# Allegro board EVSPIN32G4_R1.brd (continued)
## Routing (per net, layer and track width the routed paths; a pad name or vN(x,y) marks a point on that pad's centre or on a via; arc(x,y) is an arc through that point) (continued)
USB_DM: length 14.8
  TOP w0.305: U4.6 12.42,40.8 12.83,40.39 12.83,34.87 15.6,32.1 U5.32
USB_DP: length 17.2
  TOP w0.305: U4.4 11.88,34.68 14.72,31.84 ; U5.33 15.1,31.46 14.72,31.84 ; 14.72,31.84 R104.1
USB_RENUM: length 5.8
  TOP w0.254: R102.2 11.4,28.42 13.17,26.64 13.17,26 13.01,25.84 U5.38
V: length 34.6
  TOP w0.508: R58.1 R20.2 75.28,34 79.47,38.19 v1(80.52,38.19)
  PWR w0.508: v1(80.52,38.19) 82.55,40.23 97.88,40.23 v1(98.77,39.34)
  vias: v1(96.87,24.35) v1(96.87,23.59) v1(97.76,24.73) v1(97.76,23.72) v1(97.76,22.7) v1(98.77,38.32) v1(99.19,38.83) v1(99.41,24.73) v1(99.41,23.72) v1(99.41,22.7) v1(99.66,39.34) v1(99.66,38.32) v1(100.08,38.83) v1(100.55,39.34) v1(100.55,38.32) v1(100.97,38.83) v1(101.06,24.73) v1(101.06,23.72) v1(101.06,22.7) v1(101.44,39.34) v1(101.44,38.32) v1(101.95,24.35) v1(101.95,23.59)
VHALL: length 17.6
  TOP w0.508: C37.2 55.72,61.22 J6.4
  BOTTOM w0.762: 50.26,62.71 50.26,61.05 ; 50.26,62.71 50.51,62.45 50.53,62.45 ; 50.26,62.71 50.26,64.36 ; R84.1 50.53,62.45 ; R84.1 R89.1 ; R84.1 R87.1 ; 50.53,62.45 54.2,62.45 J6.4
VM: length 180.3
  TOP w0.508: R76.1 128.25,59.67 ; R37.2 v2(36.8,31.02)
  TOP w0.835: 102.02,58.45 C32.1 ; C32.1 104.42,58.45 ; C32.1 102.02,56.04 ; C32.1 104.42,56.04 ; C33.1 118.01,56.04 ; C33.1 115.61,58.45 ; C33.1 118.01,58.45 ; C33.1 115.61,56.04 ; 132,45.4 CON2.2 ; CON2.2 134.94,45.4 ; CON2.2 134.94,48.34 ; CON2.2 132,48.34 ; 127,45.4 CON2.1 ; CON2.1 129.94,45.4 ; CON2.1 127,48.34 ; CON2.1 129.94,48.34 ; 88.43,58.45 C31.1 ; C31.1 90.83,58.45 ; C31.1 88.43,56.04 ; C31.1 90.83,56.04
  PWR w0.381: v2(36.8,31.02) 37.62,30.19 43.53,30.19 45.18,31.84 48.05,31.84 52.58,36.37
  PWR w0.835: C33.1 118.01,58.45 ; C33.1 118.01,56.04 ; C33.1 115.61,58.45 ; C33.1 115.61,56.04 ; CON2.2 134.94,45.4 ; CON2.2 132,48.34 ; CON2.2 132,45.4 ; CON2.2 134.94,48.34 ; 102.02,58.45 C32.1 ; C32.1 102.02,56.04 ; C32.1 104.42,58.45 ; C32.1 104.42,56.04 ; CON2.1 129.94,48.34 ; CON2.1 129.94,45.4 ; CON2.1 127,45.4 ; CON2.1 127,48.34 ; C31.1 90.83,58.45 ; C31.1 88.43,58.45 ; C31.1 88.43,56.04 ; C31.1 90.83,56.04
  PWR w0.889: v2(84.42,46.96) 72.48,35.02 53.93,35.02 50.18,38.77 50.18,40.48 48.35,42.31 v2(48.35,43.53)
  BOTTOM w0.508: v2(48.35,43.53) 48.48,43.4 R1.1
  BOTTOM w0.835: C31.1 90.83,58.45 ; C31.1 90.83,56.04 ; C31.1 88.43,56.04 ; C31.1 88.43,58.45 ; CON2.2 134.94,45.4 ; CON2.2 132,45.4 ; CON2.2 134.94,48.34 ; CON2.2 132,48.34 ; 102.02,58.45 C32.1 ; C32.1 102.02,56.04 ; C32.1 104.42,56.04 ; C32.1 104.42,58.45 ; 115.61,58.45 C33.1 ; C33.1 118.01,58.45 ; C33.1 115.61,56.04 ; C33.1 118.01,56.04 ; 127,48.34 CON2.1 ; CON2.1 129.94,48.34 ; CON2.1 129.94,45.4 ; CON2.1 127,45.4
  vias: v2(82.77,59.15) v2(84.42,48.35) v2(84.84,44.42) v2(84.84,42.39) v2(85.06,47.59) v2(85.69,48.35) v2(85.69,46.96) v2(86.33,50.39) v2(86.33,47.59) v2(86.33,43.4) v2(86.96,48.35) v2(86.96,46.96) v2(87.6,47.59) v2(87.88,44.42) v2(87.88,42.39) v2(88.23,48.35) v2(88.23,46.96) v2(97.5,48.35) v2(97.5,46.96) v2(97.92,44.42) v2(97.92,42.39) v2(98.14,47.59) v2(98.77,48.35) v2(98.77,46.96) v2(99.41,50.39) v2(99.41,47.59) v2(99.41,43.4) v2(100.04,48.35) v2(100.04,46.96) v2(100.68,47.59) v2(100.97,44.42) v2(100.97,42.39) v2(101.31,48.35) v2(101.31,46.96) v2(110.58,48.35) v2(110.58,46.96) v2(111,44.42) v2(111,42.39) v2(111.22,47.59) v2(111.85,48.35) v2(111.85,46.96) v2(112.49,50.39) v2(112.49,47.59) v2(112.49,43.4) v2(113.12,48.35) v2(113.12,46.96) v2(113.76,47.59) v2(114.05,44.42) v2(114.05,42.39) v2(114.39,48.35) v2(114.39,46.96) v2(137.63,59.15)
VREF+: length 175
  TOP w0.279: 53.42,28.17 U1.26
  TOP w0.305: 53.46,28.14 53.42,28.17
  TOP w0.381: 53.46,28.14 53.46,26.56 v2(53.31,26.41)
  TOP w0.508: R43.2 v2(50.26,19.65) ; v2(53.31,26.41) 53.81,25.9 53.81,25.51 C10.2 54.23,25.46 54.83,24.86 54.83,23.17 C11.1 ; R42.2 v2(44.42,19.65) ; R41.2 v2(35.27,28.03) ; TR1.1 19.02,58.9 24.99,58.9 CN5.8
  TOP w0.762: CN5.8 27.69,56.2 C30.1 27.69,29.01 31.34,25.37 v2(34.13,25.37)
  PWR w0.305: v2(93.31,11.78) 93.18,11.91 92.17,11.91 90.52,10.25 83.41,10.25 76.29,17.37 74.39,17.37 v2(74.13,17.62)
  PWR w0.762: v2(34.13,25.37) 34.13,26.89 v2(35.27,28.03) 36.54,28.03 39.08,25.49 52.52,25.49 53.43,26.41 ; J5.6 48.48,4.54 49.62,4.54 52.16,7.08 52.16,19.4 51.91,19.65 ; 53.43,26.41 v2(53.31,26.41) ; 53.43,26.41 53.43,26.89 54.32,27.78 55.47,27.78 56.23,27.02 56.23,24.99 55.72,24.48 55.72,22.83 52.54,19.65 51.91,19.65 ; 51.91,19.65 v2(50.26,19.65) 49.12,20.8 45.56,20.8 v2(44.42,19.65)
  BOTTOM w0.305: v2(74.13,17.62) 66.64,17.62 63.21,21.05 58.41,21.05 53.31,26.16 v2(53.31,26.41) ; NTC1.1 94.14,11.78 v2(93.31,11.78)
  BOTTOM w0.508: R9.1 52.91,26.8 v2(53.31,26.41)
VREGIN: length 83.1
  TOP w0.762: 36.16,2.63 38.69,5.16 v1(47.58,5.16)
  TOP w1.016: J5.2 36.16,2.89 33.88,5.17 31.21,5.17 28.74,7.64 v1(28.74,8.63) v1(28.18,9.19)
  PWR w0.889: v1(48.4,39.97) 47.91,39.97 v1(47.72,40.16)
  PWR w1.016: v1(47.72,40.16) 47.53,40.35 42.64,40.35 41.75,39.46 41.75,37.94 41.03,37.22 39.67,37.22 37.94,38.96 30.57,38.96 26.51,34.89 26.51,20.67 24.48,18.64 24.48,12.89 v1(28.18,9.19) v1(28.74,8.63)
  BOTTOM w0.508: R66.1 v1(47.58,5.16)
  BOTTOM w0.762: v1(48.4,39.97) 48.1,39.97 46.96,41.12 R6.1
VSHUNT1N: length 92.8
  TOP w0.305: R50.1 31.84,26.38 v1(31.65,26.57) ; v1(44.92,13.97) 45.44,13.97 49.29,10.13 77.82,10.13 79.22,8.73 105.25,8.73 108.55,12.03 112.63,12.03 v1(113,11.67)
  BOTTOM w0.305: v1(44.92,13.97) 44.33,14.57 43.02,14.57 32.21,25.39 32.21,26.02 v1(31.65,26.57) ; v1(113,11.67) NET1.1
VSHUNT1P: length 92.5
  TOP w0.305: v1(44.92,15.21) 49.5,10.64 78.02,10.64 79.42,9.24 105.04,9.24 108.34,12.54 112.63,12.54 v1(113,12.9) ; R44.1 32.48,28.03 32.47,28.02 31.87,28.02 v1(31.65,27.81)
  BOTTOM w0.305: v1(44.92,15.21) 43.1,15.21 32.71,25.6 32.71,26.75 v1(31.65,27.81)
  vias: v1(109.98,14.86) v1(110.36,15.49) v1(110.74,14.86) v1(111.12,15.49) v1(111.51,14.86) v1(111.85,19.65) v1(112.36,19.15) v1(112.74,19.65) v1(113.25,19.15) v1(113.63,19.65) v1(114.14,19.15) v1(114.43,14.86) v1(114.52,19.65) v1(114.81,15.49) v1(115.19,14.86) v1(115.57,15.49) v1(115.95,14.86)
VSHUNT2N: length 60.1
  TOP w0.305: R51.1 48.06,17.18 46.77,15.88 46.77,14.89 50.39,11.27 79.47,11.27 80.87,9.87 94.84,9.87 97,12.03 99.55,12.03 v1(99.92,11.67)
  BOTTOM w0.305: v1(99.92,11.67) NET2.1
VSHUNT2P: length 59.7
  TOP w0.305: v1(47.46,15.43) 47.46,14.91 50.6,11.78 79.68,11.78 81.08,10.38 94.63,10.38 96.79,12.54 99.55,12.54 v1(99.92,12.9) ; v1(46.32,16.67) 44.92,16.67 R45.1
  BOTTOM w0.305: v1(46.32,16.67) 47.46,15.53 v1(47.46,15.43)
  vias: v1(96.9,14.86) v1(97.28,15.49) v1(97.66,14.86) v1(98.04,15.49) v1(98.43,14.86) v1(98.77,19.65) v1(99.28,19.15) v1(99.66,19.65) v1(100.17,19.15) v1(100.55,19.65) v1(101.06,19.15) v1(101.35,14.86) v1(101.44,19.65) v1(101.73,15.49) v1(102.11,14.86) v1(102.49,15.49) v1(102.87,14.86)
VSHUNT3N: length 39.7
  TOP w0.305: R52.1 51.38,16.52 51.38,16.07 54.53,12.92 80.94,12.92 81.83,12.03 v1(86.58,12.03)
  BOTTOM w0.305: NET3.1 86.83,11.78 v1(86.58,12.03)
VSHUNT3P: length 41.3
  TOP w0.305: R46.1 50.26,16.48 54.32,12.42 80.74,12.42 81.62,11.53 85.34,11.53 v1(85.71,11.16)
  BOTTOM w0.305: v1(85.71,11.16) 85.71,12.45 R35.2
  vias: v1(83.82,14.86) v1(84.2,15.49) v1(84.58,14.86) v1(84.96,15.49) v1(85.34,14.86) v1(85.69,19.65) v1(86.2,19.15) v1(86.58,19.65) v1(87.09,19.15) v1(87.47,19.65) v1(87.98,19.15) v1(88.36,19.65) v1(88.39,14.86) v1(88.77,15.49) v1(89.15,14.86) v1(89.54,15.49) v1(89.92,14.86)
W: length 51
  TOP w0.508: R60.1 R21.2 72.64,27.65 81.66,36.67 81.66,38.32 82.68,39.34 v1(85.73,39.34)
  TOP w0.581: CON1.5 129.67,36.9 ; CON1.5 127.27,36.9 ; CON1.5 129.67,34.5 ; CON1.5 128.47,34.08 ; CON1.5 128.47,37.33 ; CON1.5 126.84,35.7 ; CON1.5 130.09,35.7 ; CON1.5 127.27,34.5 ; 132.27,34.5 CON1.6 ; CON1.6 134.67,34.5 ; CON1.6 134.67,36.9 ; CON1.6 135.09,35.7 ; CON1.6 133.47,34.08 ; CON1.6 131.84,35.7 ; CON1.6 132.27,36.9 ; CON1.6 133.47,37.33
  vias: v1(83.79,24.35) v1(83.79,23.59) v1(84.68,24.73) v1(84.68,23.72) v1(84.68,22.7) v1(85.06,34.77) v1(85.06,32.23) v1(85.06,29.69) v1(85.06,27.15) v1(85.73,38.32) v1(86.11,38.83) v1(86.33,34.77) v1(86.33,32.23) v1(86.33,29.69) v1(86.33,27.15) v1(86.33,24.73) v1(86.33,23.72) v1(86.33,22.7) v1(86.61,39.34) v1(86.61,38.32) v1(87,38.83) v1(87.5,39.34) v1(87.5,38.32) v1(87.6,34.77) v1(87.6,32.23) v1(87.6,29.69) v1(87.6,27.15) v1(87.88,38.83) v1(87.98,24.73) v1(87.98,23.72) v1(87.98,22.7) v1(88.39,39.34) v1(88.39,38.32) v1(88.87,24.35) v1(88.87,23.59)
N170257: length 1.3
  TOP w0.508: D5.2 69.09,17.81 R22.1
N170269: length 46.2
  TOP w0.508: R25.2 68.8,16.41 R22.2 70.77,16.41 73.25,18.89 v1(74.13,18.89)
  PWR w0.508: v1(74.13,18.89) 79.34,18.89 81.12,17.11 105,17.11 108.45,20.56 v1(109.82,20.56)
  BOTTOM w0.508: R28.2 109.02,20.56 v1(109.82,20.56) Q4.4
N170415: length 43.9
  TOP w0.508: v1(109.86,40.1) 109.86,40.22 109.08,40.99 79.41,40.99 78.33,42.07 R10.2 68.8,42.07 R13.2
  BOTTOM w0.508: R16.2 109,40.1 v1(109.86,40.1) 110.43,40.1 Q1.4
N170423: length 1.3
  TOP w0.508: R10.1 70.26,43.53 D2.2
N174120: length 31.8
  TOP w0.508: v1(71.47,19.72) R23.2 68.8,19.72 R26.2
  PWR w0.508: v1(71.47,19.72) 79.66,19.72 81.5,17.87 92.68,17.87 95.37,20.56 v1(96.74,20.56)
  BOTTOM w0.508: R29.2 95.94,20.56 v1(96.74,20.56) Q5.4
N174124: length 1.3
  TOP w0.508: R23.1 69.09,21.11 D6.2
N174270: length 31.7
  TOP w0.508: R14.2 68.8,35.72 R11.2 75.98,35.72 79.34,39.08 80.9,39.08 82.04,40.23 93.57,40.23 v1(94.45,39.34)
  BOTTOM w0.508: v1(94.45,39.34) 94.45,39.59 95.03,40.16 R17.2 95.94,40.25 Q2.4
N174282: length 1.3
  TOP w0.508: D3.2 69.09,37.12 R11.1
N174784: length 18.8
  TOP w0.508: v1(83.66,20.54) 76.67,20.54 74.2,23.02 R24.2 68.8,23.02 R27.2
  BOTTOM w0.508: v1(83.66,20.54) 83.6,20.48 R30.2 82.86,20.56 Q6.4
N174788: length 1.3
  TOP w0.508: D7.2 69.09,24.42 R24.1
N174934: length 21.7
  TOP w0.508: v1(80.52,37.18) 80.52,36.54 73.34,29.37 R12.2 68.8,29.37 R15.2
  BOTTOM w0.508: v1(80.52,37.18) 80.9,37.18 81.41,37.69 81.41,39.34 82.23,40.16 R18.2 82.86,40.25 Q3.4
N174946: length 1.3
  TOP w0.508: R12.1 69.09,30.77 D4.2
N180167: length 2.8
  TOP w0.254: U5.2 14.1,17.97 R116.1
N180187: length 4.7
  TOP w0.254: U5.3 14.6,16.7 R117.1
N180745: length 5.9
  TOP w0.279: R106.2 19.72,15.92 ; 19.72,15.92 R105.1 ; 19.72,15.92 19.78,15.99 19.78,17.24 18.64,18.38 18.25,18.38 18.1,18.54 U5.10
N180799: length 4.1
  TOP w0.279: R114.1 18.95,30.26 18.1,29.4 U5.27
N180929: length 3.9
  TOP w0.305: J8.3 7.21,39.46 7.77,38.9 U4.3
N180941: length 4
  TOP w0.305: J8.2 7.22,40.11 7.9,40.8 U4.1
N181071: length 2
  TOP w0.305: Q7.2 8.46,31.77 R104.2
N181167: length 5.6
  TOP w0.305: Q7.1 6.63,29.94 R103.2 R102.1 9.94,27.02 R101.1
N181233: length 3.7
  TOP w0.254: U5.39 9.96,25.34 R110.1 R107.2
N181269: length 2.6
  TOP w0.508: C47.2 21.39,38.7 U3.4
N181591: length 1.3
  TOP w0.305: 2,48.48 1.94,48.42 R121.2
N181595: length 1.3
  TOP w0.305: 6.32,48.48 6.38,48.42 R122.2
N181645: length 9.3
  TOP w0.254: U5.5 15.6,18.65 15.08,18.13 15.08,14.61 C48.1 14.03,11.04 X2.1
N181657: length 9
  TOP w0.254: X2.2 15.37,11.04 C49.1 15.59,13.77 15.59,18 16.1,18.51 U5.6
N181761: length 2.4
  TOP w0.279: R119.2 10.46,22.84 U5.44
N258505: length 15.6
  TOP w0.305: J6.1 63.34,63.59 57.75,58.01 57.75,55.28 58.42,54.61 58.42,52.48
  TOP w0.381: R78.2 R81.1
N258509: length 15.4
  TOP w0.305: J6.2 60.8,63.59 55.21,58.01 55.21,54.74 55.37,54.58 55.37,52.48
  TOP w0.381: R79.2 R82.1
N258513: length 16.4
  TOP w0.305: 52.29,52.48 52.29,54.2 52.67,54.58 52.67,58.13 53.94,59.4 55.47,59.4 58.26,62.2 J6.3
  TOP w0.381: R83.1 R80.2
N261648: length 31.1
  TOP w0.305: R92.1 33.02,38.48 C40.1 33.02,41.72 R90.1 30.86,43.94 30.86,57.66 28.07,60.45 SW3.1
  TOP w0.508: SW3.2 SW3.1
N262399: length 85.7
  TOP w0.305: SW2.1 48.24,60.61 R95.1 50.45,60.61 51.27,61.44 51.27,64.23 52.55,65.5 70.71,65.5 71.09,65.12 71.09,59.53 69.82,58.26 v1(69.82,52.42) ; 58.92,23.99 59.04,24.1 59.53,24.1 v1(60.16,24.73)
  TOP w0.381: 58.92,23.99 58.92,22.33 C39.1 58.93,20.7 R97.1 ; 58.92,23.99 58.92,24.13 R96.1 ; 58.92,23.99 58.91,23.97 58.89,23.98
  TOP w0.508: SW2.1 SW2.2
  BOTTOM w0.305: v1(69.82,52.42) 69.82,30.83 63.72,24.73 v1(60.16,24.73)
N265543: length 2.3
  TOP w0.508: R77.1 R76.2
N265547: length 1.7
  TOP w0.508: LED1.2 R77.2
N274832: length 3.2
  BOTTOM w0.381: R65.1 33.62,8.08 CN6.2
N274924: length 2.4
  BOTTOM w0.381: CN6.8 48.86,6.2 R66.2
N274964: length 4.6
  BOTTOM w0.305: CN8.4 61.56,8.85 61.05,9.35 R73.1 R70.1
N274968: length 4.5
  BOTTOM w0.305: 64.1,11.02 65.11,11.02 R74.1 ; 64.1,11.02 CN8.5 ; 64.1,11.02 63.1,11.02 R71.1
N274972: length 4.6
  BOTTOM w0.305: CN8.6 67.15,9.11 R72.1 R75.1
N520147: length 1.5
  TOP w0.305: R95.2 50,63.47
N538821: length 2.4
  BOTTOM w0.305: R67.1 CN8.1
N539050: length 55.4
  BOTTOM w0.305: R69.1 36.67,38.58 34.03,35.94 34.03,32.51 30.73,29.21 30.73,25.59 40.26,16.07 40.26,14.42 41.85,12.83 51.31,12.83 52.45,13.97 55.44,13.97 57.37,12.03 57.37,10.25 CN8.3 58.89,8.6
N539062: length 55.9
  BOTTOM w0.305: R68.1 37.81,40.48 33.49,36.16 33.49,32.73 30.19,29.43 30.19,25.37 39.72,15.84 39.72,14.19 41.62,12.29 51.53,12.29 52.67,13.43 55.21,13.43 56.48,12.16 CN8.2
N683197: length 26.3
  TOP w0.279: 33.05,44.9 C38.1
  TOP w0.305: 34.04,60.45 33.4,59.82 33.4,51.69 33.05,51.34 R93.1 R91.1
  TOP w0.381: SW1.1 39.05,60.45 R94.1
  TOP w0.508: SW1.1 SW1.2
N683205: length 1.5
  TOP w0.381: R94.2 39.21,63.47
N684002: length 17.2
  TOP w0.305: C21.2 13.94,55.3 v1(13.94,56.48) TR1.2 11.65,66.26 TP3.1
  BOTTOM w0.305: R38.2 13.92,56.47 v1(13.94,56.48)
N685395: length 26.3
  TOP w0.279: v1(63.02,53.05) 63.02,52.74
  TOP w0.305: U2.7 63.4,51.79 R98.2 63.02,52.74
  BOTTOM w0.305: J7.1 70.36,53.21 68.23,53.21 66.96,51.94 64.13,51.94 v1(63.02,53.05)
N685399: length 22.8
  TOP w0.305: U2.6 64.05,51.79 R98.1 v1(64.42,53.05)
  BOTTOM w0.305: v1(64.42,53.05) 64.9,52.58 66.71,52.58 67.85,53.72 69.98,53.72 78.58,62.32 J7.2
N685471: length 2.3
  BOTTOM w0.381: R100.2 73.5,62.57 J7.4
N728166: length 35.5
  TOP w0.305: v1(65.24,32.48) R58.2 ; R59.1 v1(35.4,34.38)
  BOTTOM w0.305: v1(35.4,34.38) 36.29,35.27 40.35,35.27 41.11,36.04 42.77,36.04 47.18,31.62 64.39,31.62 v1(65.24,32.48)
N728550: length 37.7
  TOP w0.305: R61.1 v1(35.4,32.61) ; v1(64.77,28.57) R60.2
  BOTTOM w0.305: v1(35.4,32.61) 36.29,33.5 39.46,33.5 41.5,35.53 42.51,35.53 46.96,31.08 62.26,31.08 v1(64.77,28.57)
N729020: length 38.3
  TOP w0.305: v1(65.12,36.42) 65.12,37.31 66.64,38.83 R56.2 ; R57.1 v1(35.4,36.16)
  BOTTOM w0.305: v1(65.12,36.42) 60.86,32.16 47.4,32.16 42.51,37.05 36.29,37.05 v1(35.4,36.16)
N741558: length 2.2
  TOP w0.508: R105.2 v1(21.94,16.73)
  BOTTOM w0.508: v1(21.94,16.73) R108.2
N741774: length 5.3
  TOP w0.279: U1.61 50.42,41.5 50.26,41.66
  TOP w0.635: C2.2 49.75,42.39 v1(50.26,41.88) 50.26,41.66
  BOTTOM w0.508: v1(50.26,41.88) 50.51,42.13 50.51,43.26 R1.2

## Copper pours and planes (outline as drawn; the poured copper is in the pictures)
3V3_STLINK on TOP (solid shape): 3.96,52.29 0.66,52.29 0.66,55.74 3.96,55.74
3V3_STLINK on PWR: 22.83,43.02 22.83,11.52 22.57,11.27 10.76,11.27 2.13,19.91 2.13,28.8 16.6,43.27 22.57,43.27
GND on TOP (solid shape): 7.66,52.29 4.36,52.29 4.36,55.74 7.66,55.74
GND on TOP: 45.05,39.59 45.05,40.61 44.67,40.99 44.04,40.99 43.65,41.37 43.65,42.77 43.27,42.77 41.5,44.54 41.11,44.54 40.86,44.29 40.86,42.77 44.04,39.59
GND on TOP: 20.41,44.16 20.41,36.8 18.25,36.8 18.25,40.23 17.62,40.23 17.62,40.73 18.25,40.73 18.25,44.16
GND on TOP: 0.35,44.93 8.48,44.93 8.6,44.8 8.6,34.13 8.48,34 0.35,34 0.22,34.13 0.22,44.8
GND on TOP: 43.78,45.81 43.91,45.94 43.91,47.72 44.8,48.61 44.8,50.64 40.1,50.64 39.84,50.39 39.84,45.94 39.97,45.81
GND on TOP: 82.52,8.22 82.64,8.35 117.19,8.35 117.31,8.22 117.31,1.11 117.19,0.98 82.64,0.98 82.52,1.11
GND on TOP, BOTTOM, PWR: 125.19,60.67 125.19,66.13 124.93,66.39 84.17,66.39 83.91,66.13 83.91,60.67 84.17,60.42 124.93,60.42
GND on BOTTOM: 104.74,41.75 104.74,43.53 104.87,43.66 106.65,43.66 107.03,43.27 107.03,42 106.65,41.62 104.87,41.62
GND on BOTTOM: 117.82,41.75 117.82,43.53 117.95,43.66 119.73,43.66 120.11,43.27 120.11,42 119.73,41.62 117.95,41.62
GND on BOTTOM: 91.66,41.75 91.66,43.53 91.79,43.66 93.57,43.66 93.95,43.27 93.95,42 93.57,41.62 91.79,41.62
GND on BOTTOM, PWR: 82.64,8.73 117.19,8.73 117.31,8.6 117.31,1.11 117.19,0.98 82.64,0.98 82.52,1.11 82.52,8.6
GND on GND: 0.86,1.11 0.86,66.13 1.11,66.39 82.39,66.39 82.64,66.13 82.64,61.94 70.74,50.04 70.74,48.62 60.9,38.83 60.67,38.83 57.5,35.65 56.74,35.65 56.74,30.96 56.48,30.7 54.58,30.7 54.58,28.03 55.97,26.64 60.04,26.64 65.24,21.43 65.24,16.99 70.83,11.4 70.83,1.11 70.58,0.98 70.61,1.02 0.95,1.02 ; 1 cut-out
GND on GND: 70.96,1.11 70.96,11.52 65.37,17.11 65.37,21.56 60.16,26.76 56.1,26.76 54.7,28.16 54.7,30.83 56.48,30.83 56.61,30.96 56.61,36.16 58.26,36.16 60.8,38.7 61.05,38.7 70.99,48.64 70.99,50.04 82.9,61.94 82.9,66.13 83.15,66.39 133.38,66.39 138.65,61.12 138.65,6.32 133.35,1.02 71.12,1.02
GND on GND: 49.24,38.7 49.24,40.35 48.99,40.61 47.43,40.61 46.19,41.84 46.19,42.64 45.81,43.02 43.27,43.02 40.48,45.81 39.97,45.81 39.84,45.94 39.84,50.39 40.1,50.64 48.61,50.64 48.73,50.51 48.73,47.08 50.64,45.18 50.64,38.7
VCC on TOP: 44.42,47.72 46.07,47.72 46.07,43.91 46.83,43.15 46.83,42.89 48.48,41.24 48.99,41.24 49.5,40.73 49.5,40.1 48.99,40.61 47.59,40.61 46.27,41.93 46.27,42.56 45.81,43.02 43.27,43.02 42.26,44.04 42.26,45.31 43.91,45.31 44.42,45.81
VDD on TOP: 46.7,38.32 48.35,38.32 48.48,38.45 48.48,38.7 47.08,40.1 47.08,40.61 46.07,41.62 46.07,42.51 45.81,42.77 44.16,42.77 44.16,41.24 44.8,41.24 45.56,40.48 45.56,39.46
VDD on PWR: 25.37,66.39 72.1,66.39 72.36,66.13 72.36,50.64 65.63,43.91 52.29,43.91 48.99,47.21 48.99,50.64 48.73,50.89 39.97,50.89 39.59,50.51 39.59,45.94 42.77,42.77 45.94,42.77 46.07,42.64 46.07,41.75 47.97,39.85 48.1,39.85 50.51,37.43 50.51,28.8 50.13,28.42 40.61,28.42 40.23,28.03 40.23,6.44 39.34,5.56 28.92,5.56 28.86,5.62 28.79,5.68 25.11,9.36 25.11,66.13
U on BOTTOM (solid shape): 113.44,26.18 113.44,26.09 114.06,26.09 114.06,26.18 114.71,26.18 114.71,25.63 115.19,25.63 115.19,24.83 114.71,24.83 114.71,23.18 115.19,23.18 115.19,22.38 114.71,22.38 114.71,22.04 110.26,22.04 110.26,22.38 109.79,22.38 109.79,23.18 110.26,23.18 110.26,24.83 109.79,24.83 109.79,25.63 110.26,25.63 110.26,26.18 110.91,26.18 110.91,26.09 111.54,26.09 111.54,26.18 112.11,26.18 112.11,26.08 112.87,26.08 112.87,26.18
U on TOP: 108.42,22.07 118.71,22.07 123.16,17.62 136.49,17.62 136.62,17.75 136.62,28.42 136.49,28.54 124.05,28.54 120.62,25.11 108.42,25.11 108.3,24.99 108.3,22.19
U on BOTTOM: 108.3,22.19 108.42,22.07 118.71,22.07 123.16,17.62 136.49,17.62 136.62,17.75 136.62,28.42 136.49,28.54 127.35,28.54 126.24,29.65 126.24,40.61 125.98,40.86 111.47,40.86 111.47,39.46 111.22,39.21 108.42,39.21 108.3,39.08
V on BOTTOM (solid shape): 100.36,26.18 100.36,26.09 100.98,26.09 100.98,26.18 101.63,26.18 101.63,25.63 102.11,25.63 102.11,24.83 101.63,24.83 101.63,23.18 102.11,23.18 102.11,22.38 101.63,22.38 101.63,22.04 97.18,22.04 97.18,22.38 96.71,22.38 96.71,23.18 97.18,23.18 97.18,24.83 96.71,24.83 96.71,25.63 97.18,25.63 97.18,26.18 97.83,26.18 97.83,26.09 98.46,26.09 98.46,26.18 99.03,26.18 99.03,26.08 99.79,26.08 99.79,26.18
V on TOP: 94.2,22.07 107.41,22.07 107.54,22.19 107.54,24.99 107.41,25.11 96.49,25.11 94.07,22.7 94.07,22.19
V on BOTTOM: 93.57,22.07 107.41,22.07 107.54,22.19 107.54,40.73 107.41,40.86 98.39,40.86 98.39,39.46 98.14,39.21 95.34,39.21 93.44,37.31 93.44,22.19
V on PWR: 93.44,22.19 93.57,22.07 121.12,22.07 126.97,27.91 136.36,27.91 136.62,28.16 136.62,33.24 136.36,33.5 126.97,33.5 121.51,38.96 109.35,38.96 108.46,39.85 96.11,39.85 93.44,37.18
VM on BOTTOM (solid shape): 87.28,45.87 87.28,45.77 87.9,45.77 87.9,45.87 88.55,45.87 88.55,45.31 89.03,45.31 89.03,44.51 88.55,44.51 88.55,42.86 89.03,42.86 89.03,42.06 88.55,42.06 88.55,41.73 84.1,41.73 84.1,42.06 83.63,42.06 83.63,42.86 84.1,42.86 84.1,44.51 83.63,44.51 83.63,45.31 84.1,45.31 84.1,45.87 84.75,45.87 84.75,45.77 85.38,45.77 85.38,45.87 85.95,45.87 85.95,45.76 86.71,45.76 86.71,45.87
VM on BOTTOM (solid shape): 100.36,45.87 100.36,45.77 100.98,45.77 100.98,45.87 101.63,45.87 101.63,45.31 102.11,45.31 102.11,44.51 101.63,44.51 101.63,42.86 102.11,42.86 102.11,42.06 101.63,42.06 101.63,41.73 97.18,41.73 97.18,42.06 96.71,42.06 96.71,42.86 97.18,42.86 97.18,44.51 96.71,44.51 96.71,45.31 97.18,45.31 97.18,45.87 97.83,45.87 97.83,45.77 98.46,45.77 98.46,45.87 99.03,45.87 99.03,45.76 99.79,45.76 99.79,45.87
VM on BOTTOM (solid shape): 113.44,45.87 113.44,45.77 114.06,45.77 114.06,45.87 114.71,45.87 114.71,45.31 115.19,45.31 115.19,44.51 114.71,44.51 114.71,42.86 115.19,42.86 115.19,42.06 114.71,42.06 114.71,41.73 110.26,41.73 110.26,42.06 109.79,42.06 109.79,42.86 110.26,42.86 110.26,44.51 109.79,44.51 109.79,45.31 110.26,45.31 110.26,45.87 110.91,45.87 110.91,45.77 111.54,45.77 111.54,45.87 112.11,45.87 112.11,45.76 112.87,45.76 112.87,45.87
VM on TOP: 82.39,59.78 138.02,59.78 138.27,59.53 138.27,44.54 138.02,44.29 119.22,44.29 118.58,43.66 118.58,43.62 116.71,41.75 107.79,41.75 107.54,42 107.54,43.66 107.03,44.16 106.01,44.16 105.5,43.66 105.5,42 105.25,41.75 94.71,41.75 94.45,42 94.45,43.66 93.95,44.16 92.93,44.16 92.42,43.66 92.42,42 92.17,41.75 82.3,41.75 82.14,41.91 82.14,59.53
VM on BOTTOM: 82.39,59.78 138.02,59.78 138.27,59.53 138.27,44.54 138.02,44.29 117.7,44.29 117.31,43.91 117.31,41.75 107.79,41.75 107.54,42 107.54,43.66 107.03,44.16 104.49,44.16 104.23,43.91 104.23,41.75 94.71,41.75 94.45,42 94.45,43.66 93.95,44.16 91.41,44.16 91.15,43.91 91.15,41.75 82.26,41.75 82.14,41.88 82.14,59.53
VM on PWR: 82.39,59.78 138.27,59.78 138.52,59.53 138.52,44.54 138.27,44.29 119.22,44.29 116.68,41.75 82.26,41.75 82.14,41.88 82.14,59.53
VREGIN on TOP: 48.23,40.35 48.86,40.35 48.99,40.23 48.99,38.83 48.61,38.83 47.34,40.1 47.34,40.46 47.36,40.48 48.1,40.48
VSHUNT1P on TOP: 123.16,16.1 118.08,21.18 111.73,21.18 110.2,19.65 108.55,19.65 108.42,19.53 108.42,13.05 108.55,12.92 112.23,12.92 112.74,13.43 113.25,13.43 114.14,12.54 123.03,12.54 123.16,12.67
VSHUNT1P on BOTTOM: 123.16,16.1 118.08,21.18 111.47,21.18 111.47,19.78 111.22,19.53 108.55,19.53 107.15,18.13 107.15,12.54 123.03,12.54 123.16,12.67
VSHUNT1P on PWR: 111.73,21.18 118.08,21.18 123.16,16.1 123.16,12.67 123.03,12.54 113.33,12.54 113.46,12.71 113.5,12.92 113,13.43 112.49,12.92 112.53,12.71 112.66,12.54 108.55,12.54 108.42,12.67 108.42,19.53 108.55,19.65 110.2,19.65
VSHUNT2P on TOP: 107.66,21.05 107.54,21.18 98.65,21.18 97.12,19.65 96.36,19.65 94.84,21.18 93.82,21.18 93.69,21.05 93.69,13.05 93.82,12.92 99.15,12.92 99.66,13.43 100.17,13.43 101.06,12.54 107.03,12.54 107.66,13.18
VSHUNT2P on BOTTOM: 107.66,21.05 107.54,21.18 98.39,21.18 98.39,19.78 98.14,19.53 95.09,19.53 93.69,18.13 93.69,12.54 106.65,12.54 106.65,18.64 107.66,19.65
VSHUNT2P on PWR: 98.65,21.18 107.54,21.18 107.66,21.05 107.66,12.67 107.54,12.54 100.25,12.54 100.38,12.71 100.42,12.92 99.92,13.43 99.41,12.92 99.45,12.71 99.58,12.54 95.34,12.54 95.22,12.67 95.22,19.4 95.47,19.65 97.12,19.65
VSHUNT3P on TOP: 92.93,12.67 92.93,21.05 92.8,21.18 85.56,21.18 84.04,19.65 78.45,19.65 78.2,19.4 78.2,13.56 78.33,13.43 81.25,13.43 82.14,12.54 92.8,12.54
VSHUNT3P on BOTTOM: 94.45,21.18 85.31,21.18 85.31,19.78 85.06,19.53 78.33,19.53 78.2,19.4 78.2,12.67 78.33,12.54 93.18,12.54 93.18,18.64 94.58,20.03 94.58,21.05
VSHUNT3P on PWR: 92.8,21.18 85.56,21.18 84.04,19.65 81.12,19.65 80.99,19.53 80.99,19.27 80.1,18.76 80.1,14.83 82.39,12.54 91.41,12.54 91.91,13.05 91.91,16.6 92.93,17.62 92.93,21.05
W on BOTTOM (solid shape): 87.28,26.18 87.28,26.09 87.9,26.09 87.9,26.18 88.55,26.18 88.55,25.63 89.03,25.63 89.03,24.83 88.55,24.83 88.55,23.18 89.03,23.18 89.03,22.38 88.55,22.38 88.55,22.04 84.1,22.04 84.1,22.38 83.63,22.38 83.63,23.18 84.1,23.18 84.1,24.83 83.63,24.83 83.63,25.63 84.1,25.63 84.1,26.18 84.75,26.18 84.75,26.09 85.38,26.09 85.38,26.18 85.95,26.18 85.95,26.08 86.71,26.08 86.71,26.18
W on TOP: 78.2,22.19 78.33,22.07 92.55,22.07 96.11,25.62 119.98,25.62 127.22,32.86 136.62,32.86 136.75,32.99 136.75,40.48 136.62,40.61 119,40.61 117.35,38.96 103.47,38.96 101.95,37.43 94.96,37.43 92.8,39.59 85.73,39.59 85.09,38.96 82.9,38.96 82.14,38.19 82.14,36.54 78.2,32.61
W on BOTTOM: 78.33,22.07 92.55,22.07 92.68,22.19 92.68,40.73 92.55,40.86 85.31,40.86 85.31,39.46 85.06,39.21 82.26,39.21 82.14,39.08 82.14,37.31 81.12,36.29 78.33,36.29 78.2,36.16 78.2,22.19
W on PWR: 78.2,22.19 78.33,22.07 92.55,22.07 92.68,22.19 92.68,39.37 92.46,39.59 83.15,39.59 82.14,38.58 82.14,37.31 81.12,36.29 78.33,36.29 78.2,36.16
N181591 on TOP (solid shape): 3.96,48.34 0.66,48.34 0.66,51.79 3.96,51.79
N181595 on TOP (solid shape): 7.66,48.34 4.36,48.34 4.36,51.79 7.66,51.79

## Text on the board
BOTTOM: EVSPIN32G4 R1 BOT  21-Jan-2021  Rigo | 4
Ref Des/Assembly Bottom: EVSPIN32G4 R1 ASB  21-Jan-2021  Rigo
Package Geometry/Pastemask Bottom: EVSPIN32G4 R1 PMB  21-Jan-2021  Rigo
Ref Des/Silkscreen Bottom: EVSPIN32G4 R1 SSB  21-Jan-2021  Rigo
User.Comments: EVSPIN32G4 R1 SMT  21-Jan-2021  Rigo | EVSPIN32G4 R1 SMB  21-Jan-2021  Rigo
TOP: EVSPIN32G4 R1 TOP  21-Jan-2021  Rigo | 1
Ref Des/Assembly Top: EVSPIN32G4 R1 AST  21-Jan-2021  Rigo | HEATSINK
Package Geometry/Pastemask Top: EVSPIN32G4 R1 PMT  21-Jan-2021  Rigo
Ref Des/Silkscreen Top: RESET | OPP1 | USER1/WAKE | GND | OPO1 | OPP2 | USER2 | OPP3 | VH. | H3 | H2 | H1 | VDSMON | DIS | SH | L | H | VM | PGND | W | V | U | SPEED | DAC1 | DAC2 | VCC | VREG | VDD | VBAT | VDDA | OPO2 | VREF | OPO3 | Evaluation board | Rev. 1 | EVSPIN32G4
GND: EVSPIN32G4 R1 GND  21-Jan-2021  Rigo | 2
PWR: EVSPIN32G4 R1 PWR  21-Jan-2021  Rigo | 3
XSECTION_CHART: *  SURFACE - AIR 0 MIL | L1 TOP CONDUCTOR - 2OZ_COPPER 2.8 MIL | *  DIELECTRIC - FR-4_NO_FLOW_PREPREG 14.17 MIL | L2 GND CONDUCTOR - 2OZ_COPPER 2.8 MIL | *  DIELECTRIC - FR-4 23.82 MIL | L3 PWR CONDUCTOR - 2OZ_COPPER 2.8 MIL | L4 BOTTOM CONDUCTOR - 2OZ_COPPER 2.8 MIL | DESIGN CROSS SECTION CHART | ___________________________ | TOTAL THICKNESS 63.36 MIL | 1-4
PAGE_OUTLINE: 21-Jan-2021 | 1.0 | STSPIN32G4 | EVSPIN32G4
COMPVAL_TYPE_TOP: 1 : 1 | DRILLING AND PROFILING
User.9: FIGURE | FINISHED_SIZE | 11.81 | 15.75 | 27.56 | 31.5 | 35.43 | 39.37 | 51.18 | 125.98 | 47.24x21.65 | 55.12x33.46 | DRILL CHART: TOP to BOTTOM | ALL UNITS ARE IN MILS | PLATED | NON-PLATED | QTY | 258 | 200 | 20 | 2 | 24 | 38 | 10 | 8 | 566 | TOTAL HOLES:
User.10: 1.5 : 1 | - "D" holes must remain OPEN after solder phase. | - When THT components aren't mounted, | - Heatsink must be cutted and drilled as BOM's indication | - Insulator must be cutted and drilled (See Heatsink) | - Stick the insulator on bottom side of Heatsink | - Put Heatsink on Top side of P.C.B. | - Insert 4 screws from bottom side of P.C.B. | your holes must remains OPEN after solder phase. | screwing them in the Heatsink | ASSEMBLY DRAWING
